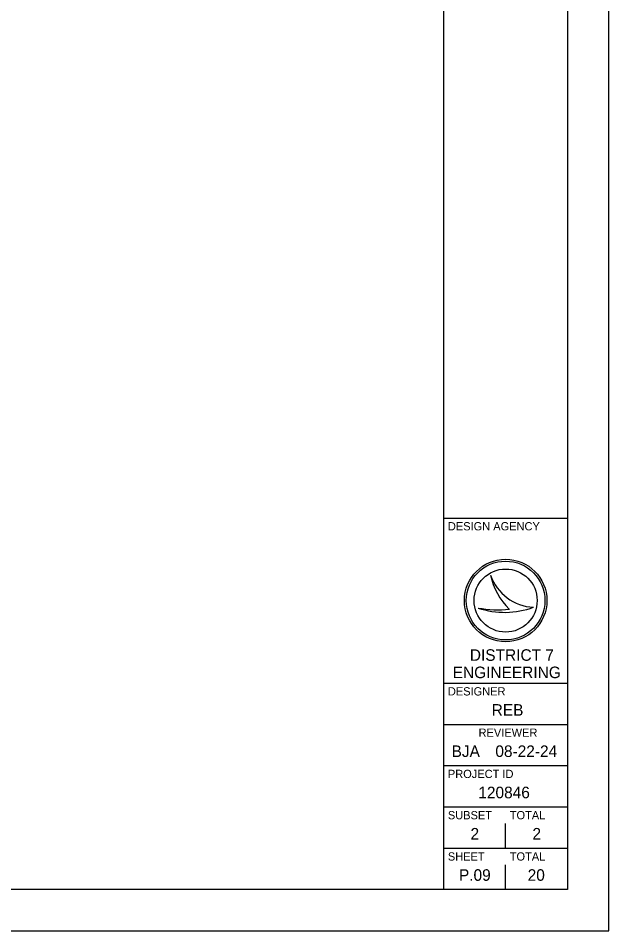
# Model space of a CAD drawing. Extents: x 0 to 68, y 0 to 44.
# Drawn here: x 53.68 to 68, y 0 to 22.11 of the extents above; entities that cross this region are included whole.
import ezdxf

# ---------------------------------------------------------------- set-up
doc = ezdxf.new("R2010")
doc.units = 0
for name, color, linetype in [('Default', 7, 'Continuous'), ('SH_Border', 7, 'Continuous'), ('SH_Cut_Line', 7, 'Continuous'), ('SH_Data', 7, 'Continuous'), ('SH_Text', 7, 'Continuous')]:
    doc.layers.add(name, color=color, linetype=linetype)

msp = doc.modelspace()

# ---------------------------------------------------------------- linework, layer by layer
at = {"layer": 'SH_Border'}
for p, q in [((64, 1), (64, 43)), ((64, 10), (67, 10)), ((64, 6), (67, 6)), ((64, 5), (67, 5)), ((64, 4), (67, 4)), ((64, 3), (67, 3)), ((64, 2), (67, 2))]:
    msp.add_line(p, q, dxfattribs=at)
msp.add_lwpolyline([(3, 43), (67, 43), (67, 1), (3, 1)], close=True, dxfattribs=at)
at = {"layer": 'SH_Cut_Line'}
msp.add_lwpolyline([(0, 0), (68, 0), (68, 44), (0, 44)], close=True, dxfattribs=at)
at = {"layer": 'SH_Data'}
for p, q in [((65.135, 8.619), (65.135, 8.619)), ((65.5, 8), (65.5, 8)), ((64.834, 7.819), (64.834, 7.819)), ((66.175, 7.837), (66.175, 7.837)), ((65.5, 2), (65.5, 2.6)), ((65.5, 1), (65.5, 1.6)), ((64.75, 1.35), (64.75, 1.35))]:
    msp.add_line(p, q, dxfattribs=at)
for radius in [1, 0.954, 0.954, 0.764]:
    msp.add_circle((65.5, 8), radius, dxfattribs=at)
for centre, radius, start, end in [((66.232, 8.995), 1.16, 198.9257, 198.9319), ((66.693, 8.94), 1.591, 191.6379, 191.6421), ((66.232, 8.995), 1.16, 198.9319, 267.1657), ((66.693, 8.94), 1.591, 191.6421, 226.0947), ((65.479, 9.74), 2.026, 251.4576, 290.0832), ((65.296, 10.309), 2.532, 259.4964, 259.4995), ((65.479, 9.74), 2.026, 251.4527, 251.4576), ((65.296, 10.309), 2.532, 259.4995, 276.6672)]:
    msp.add_arc(centre, radius, start, end, dxfattribs=at)

# ---------------------------------------------------------------- texts
at = {"layer": 'Default'}
msp.add_text('120846', height=0.28, dxfattribs=at).set_placement((64.838, 3.21))
at = {"layer": 'SH_Data'}
for s, height, p in [('DESIGN AGENCY', 0.2, (64.1, 9.7)), ('DESIGNER', 0.2, (64.1, 5.7)), ('REB', 0.28, (65.162, 5.21)), ('REVIEWER', 0.2, (64.844, 4.7)), ('BJA', 0.28, (64.19, 4.21)), ('08-22-24', 0.28, (65.251, 4.21)), ('PROJECT ID', 0.2, (64.1, 3.7)), ('SUBSET', 0.2, (64.1, 2.7)), ('TOTAL', 0.2, (65.6, 2.7)), ('2', 0.28, (64.65, 2.21)), ('2', 0.28, (66.15, 2.21)), ('SHEET', 0.2, (64.1, 1.7)), ('TOTAL', 0.2, (65.6, 1.7)), ('P.09', 0.28, (64.368, 1.21)), ('20', 0.28, (66.034, 1.21))]:
    msp.add_text(s, height=height, dxfattribs=at).set_placement(p)
at = {"layer": 'SH_Text'}
for s, p in [('    DISTRICT 7 ', (64.216, 6.54)), ('ENGINEERING', (64.216, 6.12))]:
    msp.add_text(s, height=0.28, dxfattribs=at).set_placement(p)

doc.saveas('drawing.dxf')
